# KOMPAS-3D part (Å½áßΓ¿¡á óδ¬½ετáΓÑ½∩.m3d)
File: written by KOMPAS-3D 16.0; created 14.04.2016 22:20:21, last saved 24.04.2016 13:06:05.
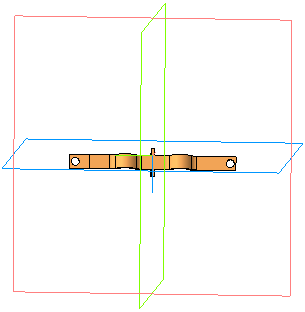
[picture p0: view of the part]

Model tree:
1. Эскиз:1
2. Операция выдавливания:1
     Расстояние 1 = 2.5; Расстояние 2 = 5; Угол 2 = 2
3. Скругление:3
     Радиус = 1
4. Скругление:4
     Радиус = 1
5. Эскиз:2
6. Операция выдавливания:2
     Расстояние 1 = 1.25; Расстояние 2 = 3.75
7. Операция выдавливания:3
     Расстояние 1 = 3.5; Расстояние 2 = 3.75
8. Операция выдавливания:4
     Расстояние 1 = 3.5; Расстояние 2 = 3.75
9. Эскиз:5
10. Вырезать элемент выдавливания:3
     Расстояние 1 = 10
